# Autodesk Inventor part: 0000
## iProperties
Shininess: 64.0
Length Units: 11269
Angle Units: 11279
Time Units: 11290
Mass Units: 11283
Length Display Precision: 3
Angle Display Precision: 2
Compacted: True
Part Number: 0000
Document SubType Name: Modeling
Created: 2004-02
Material: Par défaut
Project: GDB000
Designer: Gilles Glemarec
Manufacturer: Standard
Standards Organization: Custom
Density: 0.0
Volumn: 0.0
Area: 0.0
PropertySet Name: Model Information
Control State: 0
Master: False
Checked Out: False
Observations: -
Revision Number: 00
